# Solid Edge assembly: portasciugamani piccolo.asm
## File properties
Title: P.Asciugamani
Author: i.fialdini
Template: iso assembly.asm
Last saved by: a.ravenna
Revision: 6
Application: Solid Edge
Tipo di contenuto documento: 1
Document Number: 6007
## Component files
portasciugamani piccolo.par
portasciugamani piccolo_0.par
portasciugamani piccolo_1.par
portasciugamani piccolo_2.par
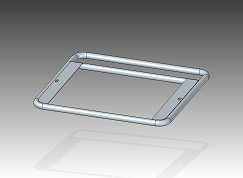
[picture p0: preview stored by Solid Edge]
